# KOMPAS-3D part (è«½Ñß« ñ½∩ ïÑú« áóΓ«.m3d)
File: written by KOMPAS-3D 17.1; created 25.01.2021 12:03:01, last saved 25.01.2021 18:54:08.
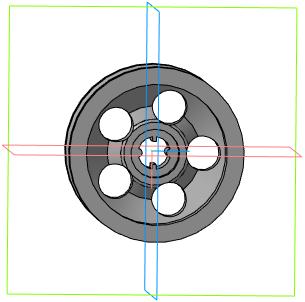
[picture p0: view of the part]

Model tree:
1. Эскиз:1
2. Элемент вращения:2
     Угол 1 = 360
3. Эскиз:2
4. Элемент выдавливания:1
     Расстояние 2 = 20
5. Эскиз:3
6. Элемент выдавливания:2
     Расстояние 1 = -20
7. Эскиз:4
8. Элемент выдавливания:3
     Расстояние 2 = 17
9. Эскиз:5
10. Элемент выдавливания:4
     Расстояние 2 = 6.4
11. Фаска:2
     Угол = 35.8377; Длина 1 = 9; Длина 2 = 6.5
12. Фаска:3
     Угол = 55.008; Длина 1 = 7; Длина 2 = 10
13. Эскиз:6
14. Элемент выдавливания:5
     Расстояние 2 = 20
15. Массив по концентрической сетке:1  (with: Элемент выдавливания:5)  (5 pattern instances)
     Шаг 2 = 360
16. Фаска:4
     Угол = 71.5651; Длина 1 = 2; Длина 2 = 6
17. Эскиз:7
18. Элемент выдавливания:6
     Расстояние 2 = 1
19. Скругление:1
     Радиус = 0.25
20. Скругление:2
     Радиус = 0.5
21. Скругление:3
     Радиус = 0.5
22. Скругление:4
     Радиус = 0.5
23. Эскиз:8
24. Элемент выдавливания:7
     Расстояние 2 = 10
